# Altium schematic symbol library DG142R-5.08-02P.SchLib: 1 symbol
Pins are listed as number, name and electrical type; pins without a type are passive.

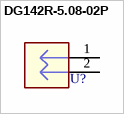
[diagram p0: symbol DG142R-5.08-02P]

## DG142R-5.08-02P
designator U?  (value not drawn)
DG129-5.0-03P-14-00AH
footprint DG142R-5.08-02P
pins: 1, 2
